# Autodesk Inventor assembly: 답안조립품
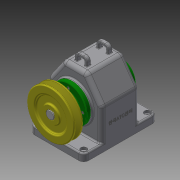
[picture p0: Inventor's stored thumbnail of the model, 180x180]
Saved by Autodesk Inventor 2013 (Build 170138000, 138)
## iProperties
Created: 2016-12
Part Number: 답안조립품
Document SubType Name: Assembly
Designer: Administrator
Author: Administrator
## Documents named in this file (15)
- C:\Users\Administrator\Desktop\461208V1004\답안조립품.iam
- C:\Users\Administrator\Desktop\461208V1004\본체_1.ipt
- C:\Users\Administrator\Desktop\461208V1004\V-벨트풀리.ipt
- C:\Users\Administrator\Desktop\461208V1004\뒤커버.ipt
- C:\Users\Administrator\Desktop\461208V1004\멈춤나사 - M4x10.ipt
- C:\Users\Administrator\Desktop\461208V1004\베어링 6203.ipt
- C:\Users\Administrator\Desktop\461208V1004\볼트 M3 x 8.ipt
- C:\Users\Administrator\Desktop\461208V1004\볼트 M3 x 10.ipt
- C:\Users\Administrator\Desktop\461208V1004\부시.ipt
- C:\Users\Administrator\Desktop\461208V1004\스퍼기어.ipt
- C:\Users\Administrator\Desktop\461208V1004\앞커버.ipt
- C:\Users\Administrator\Desktop\461208V1004\오일씰 28 40 8.ipt
- C:\Users\Administrator\Desktop\461208V1004\축.ipt
- C:\Users\Administrator\Desktop\461208V1004\키 - 5 x 5 x 18.ipt
- C:\Users\Administrator\Desktop\461208V1004\키 - 6 x 6 x 22.ipt
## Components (9 placed, 3 different names)
1. V-벨트풀리:1
2. ISO 4762 M3 x 10:1
3. ISO 4762 M3 x 10:2
4. ISO 4762 M3 x 10:3
5. ISO 4762 M3 x 10:4
6. ISO 4762 M3 x 8:1
7. ISO 4762 M3 x 8:2
8. ISO 4762 M3 x 8:3
9. ISO 4762 M3 x 8:4
